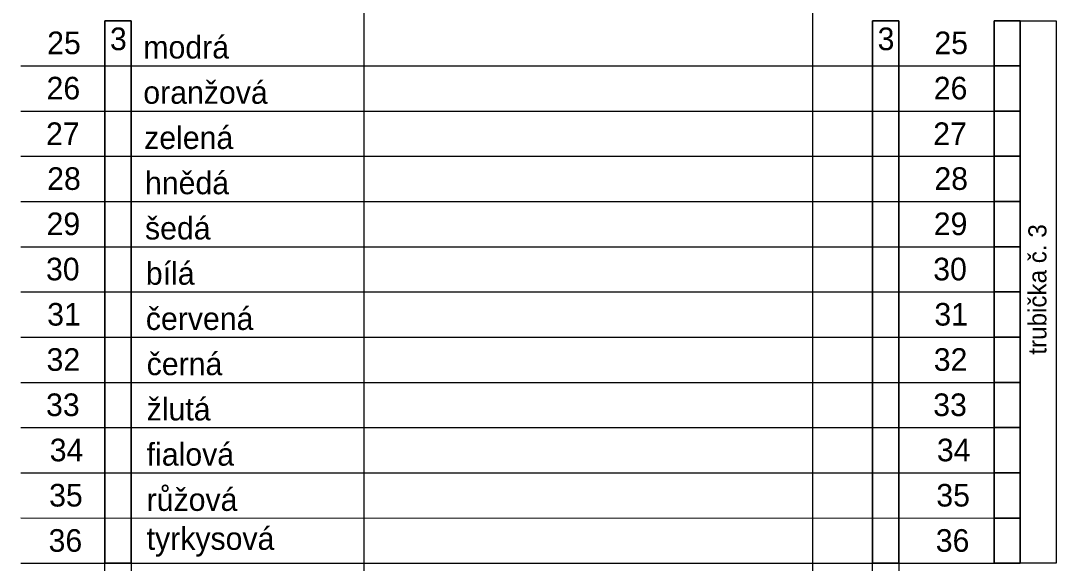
# Model space of a CAD drawing. Extents: x 1901 to 2519, y -3585 to -3154.
# Drawn here: x 2032.8 to 2113, y -3329.7 to -3287.5 of the extents above; entities that cross this region are included whole.
import ezdxf

# ---------------------------------------------------------------- set-up
doc = ezdxf.new("R2010")
doc.units = 0
doc.layers.add('rozvláknění', color=7, linetype='Continuous')

msp = doc.modelspace()

# ---------------------------------------------------------------- linework, layer by layer
at = {"layer": 'rozvláknění'}
for p, q in [((2032.823, -3291.004), (2108.565, -3291.007)), ((2032.823, -3294.523), (2108.565, -3294.525)), ((2032.823, -3298.041), (2108.565, -3298.043)), ((2032.823, -3301.559), (2108.565, -3301.561)), ((2032.823, -3305.077), (2108.565, -3305.079)), ((2032.823, -3308.595), (2108.565, -3308.597)), ((2032.823, -3312.114), (2108.565, -3312.116)), ((2032.823, -3315.632), (2108.565, -3315.634)), ((2032.823, -3319.15), (2108.565, -3319.152)), ((2032.823, -3322.668), (2108.565, -3322.67)), ((2032.823, -3326.186), (2108.565, -3326.188)), ((2032.823, -3329.705), (2108.565, -3329.707))]:
    msp.add_line(p, q, dxfattribs=at)
for points in [[(2014.869, -3178.545), (2059.522, -3178.544), (2059.522, -3570.656), (2014.869, -3570.656)], [(2094.462, -3178.545), (2128.46, -3178.544), (2128.46, -3571.465), (2094.462, -3571.465)], [(2041.391, -3371.961), (2039.35, -3371.961), (2039.35, -3287.488), (2041.391, -3287.488)], [(2041.391, -3329.707), (2039.35, -3329.707), (2039.35, -3287.488), (2041.391, -3287.488)], [(2101.143, -3371.961), (2099.102, -3371.961), (2099.102, -3287.488), (2101.143, -3287.488)], [(2101.143, -3329.707), (2099.102, -3329.707), (2099.102, -3287.488), (2101.143, -3287.488)], [(2108.565, -3287.488), (2110.606, -3287.488), (2110.606, -3291.007), (2108.565, -3291.007)], [(2108.565, -3287.488), (2110.606, -3287.488), (2110.606, -3291.007), (2108.565, -3291.007)], [(2110.606, -3287.488), (2113.393, -3287.488), (2113.393, -3329.703), (2110.606, -3329.703)], [(2108.565, -3291.007), (2110.606, -3291.007), (2110.606, -3294.525), (2108.565, -3294.525)], [(2108.565, -3291.007), (2110.606, -3291.007), (2110.606, -3294.525), (2108.565, -3294.525)], [(2108.565, -3294.525), (2110.606, -3294.525), (2110.606, -3298.043), (2108.565, -3298.043)], [(2108.565, -3294.525), (2110.606, -3294.525), (2110.606, -3298.043), (2108.565, -3298.043)], [(2108.565, -3298.043), (2110.606, -3298.043), (2110.606, -3301.561), (2108.565, -3301.561)], [(2108.565, -3298.043), (2110.606, -3298.043), (2110.606, -3301.561), (2108.565, -3301.561)], [(2108.565, -3301.561), (2110.606, -3301.561), (2110.606, -3305.079), (2108.565, -3305.079)], [(2108.565, -3301.561), (2110.606, -3301.561), (2110.606, -3305.079), (2108.565, -3305.079)], [(2108.565, -3305.079), (2110.606, -3305.079), (2110.606, -3308.597), (2108.565, -3308.597)], [(2108.565, -3305.079), (2110.606, -3305.079), (2110.606, -3308.597), (2108.565, -3308.597)], [(2108.565, -3308.597), (2110.606, -3308.597), (2110.606, -3312.116), (2108.565, -3312.116)], [(2108.565, -3308.597), (2110.606, -3308.597), (2110.606, -3312.116), (2108.565, -3312.116)], [(2108.565, -3312.116), (2110.606, -3312.116), (2110.606, -3315.634), (2108.565, -3315.634)], [(2108.565, -3312.116), (2110.606, -3312.116), (2110.606, -3315.634), (2108.565, -3315.634)], [(2108.565, -3315.634), (2110.606, -3315.634), (2110.606, -3319.152), (2108.565, -3319.152)], [(2108.565, -3315.634), (2110.606, -3315.634), (2110.606, -3319.152), (2108.565, -3319.152)], [(2108.565, -3319.152), (2110.606, -3319.152), (2110.606, -3322.67), (2108.565, -3322.67)], [(2108.565, -3319.152), (2110.606, -3319.152), (2110.606, -3322.67), (2108.565, -3322.67)], [(2108.565, -3322.67), (2110.606, -3322.67), (2110.606, -3326.188), (2108.565, -3326.188)], [(2108.565, -3322.67), (2110.606, -3322.67), (2110.606, -3326.188), (2108.565, -3326.188)], [(2108.565, -3326.188), (2110.606, -3326.188), (2110.606, -3329.707), (2108.565, -3329.707)], [(2108.565, -3326.188), (2110.606, -3326.188), (2110.606, -3329.707), (2108.565, -3329.707)]]:
    msp.add_lwpolyline(points, close=True, dxfattribs=at)
for points in [[(2041.391, -3287.488), (2039.35, -3287.488), (2039.35, -3329.707), (2041.391, -3329.707), (2041.391, -3287.488)], [(2041.391, -3287.488), (2039.35, -3287.488), (2039.35, -3329.707), (2041.391, -3329.707), (2041.391, -3287.488)], [(2041.391, -3287.488), (2039.35, -3287.488), (2039.35, -3329.707), (2041.391, -3329.707), (2041.391, -3287.488)], [(2041.391, -3287.488), (2039.35, -3287.488), (2039.35, -3329.707), (2041.391, -3329.707), (2041.391, -3287.488)], [(2041.391, -3287.488), (2039.35, -3287.488), (2039.35, -3329.707), (2041.391, -3329.707), (2041.391, -3287.488)], [(2041.391, -3287.488), (2039.35, -3287.488), (2039.35, -3329.707), (2041.391, -3329.707), (2041.391, -3287.488)], [(2101.143, -3287.488), (2099.102, -3287.488), (2099.102, -3329.707), (2101.143, -3329.707), (2101.143, -3287.488)], [(2101.143, -3287.488), (2099.102, -3287.488), (2099.102, -3329.707), (2101.143, -3329.707), (2101.143, -3287.488)], [(2101.143, -3287.488), (2099.102, -3287.488), (2099.102, -3329.707), (2101.143, -3329.707), (2101.143, -3287.488)], [(2101.143, -3287.488), (2099.102, -3287.488), (2099.102, -3329.707), (2101.143, -3329.707), (2101.143, -3287.488)], [(2101.143, -3287.488), (2099.102, -3287.488), (2099.102, -3329.707), (2101.143, -3329.707), (2101.143, -3287.488)], [(2101.143, -3287.488), (2099.102, -3287.488), (2099.102, -3329.707), (2101.143, -3329.707), (2101.143, -3287.488)], [(2108.565, -3291.007), (2110.606, -3291.007), (2110.606, -3287.488), (2108.565, -3287.488), (2108.565, -3291.007)], [(2108.565, -3291.007), (2110.606, -3291.007), (2110.606, -3287.488), (2108.565, -3287.488), (2108.565, -3291.007)], [(2108.565, -3291.007), (2110.606, -3291.007), (2110.606, -3287.488), (2108.565, -3287.488), (2108.565, -3291.007)], [(2108.565, -3291.007), (2110.606, -3291.007), (2110.606, -3287.488), (2108.565, -3287.488), (2108.565, -3291.007)], [(2108.565, -3291.007), (2110.606, -3291.007), (2110.606, -3287.488), (2108.565, -3287.488), (2108.565, -3291.007)], [(2108.565, -3291.007), (2110.606, -3291.007), (2110.606, -3287.488), (2108.565, -3287.488), (2108.565, -3291.007)], [(2108.565, -3291.007), (2110.606, -3291.007), (2110.606, -3287.488), (2108.565, -3287.488), (2108.565, -3291.007)], [(2108.565, -3291.007), (2110.606, -3291.007), (2110.606, -3287.488), (2108.565, -3287.488), (2108.565, -3291.007)], [(2108.565, -3291.007), (2110.606, -3291.007), (2110.606, -3287.488), (2108.565, -3287.488), (2108.565, -3291.007)], [(2108.565, -3291.007), (2110.606, -3291.007), (2110.606, -3287.488), (2108.565, -3287.488), (2108.565, -3291.007)], [(2108.565, -3291.004), (2108.565, -3326.204)], [(2108.565, -3294.525), (2110.606, -3294.525), (2110.606, -3291.007), (2108.565, -3291.007), (2108.565, -3294.525)], [(2108.565, -3294.525), (2110.606, -3294.525), (2110.606, -3291.007), (2108.565, -3291.007), (2108.565, -3294.525)], [(2108.565, -3294.525), (2110.606, -3294.525), (2110.606, -3291.007), (2108.565, -3291.007), (2108.565, -3294.525)], [(2108.565, -3294.525), (2110.606, -3294.525), (2110.606, -3291.007), (2108.565, -3291.007), (2108.565, -3294.525)], [(2108.565, -3294.525), (2110.606, -3294.525), (2110.606, -3291.007), (2108.565, -3291.007), (2108.565, -3294.525)], [(2108.565, -3294.525), (2110.606, -3294.525), (2110.606, -3291.007), (2108.565, -3291.007), (2108.565, -3294.525)], [(2108.565, -3294.525), (2110.606, -3294.525), (2110.606, -3291.007), (2108.565, -3291.007), (2108.565, -3294.525)], [(2108.565, -3294.525), (2110.606, -3294.525), (2110.606, -3291.007), (2108.565, -3291.007), (2108.565, -3294.525)], [(2108.565, -3294.525), (2110.606, -3294.525), (2110.606, -3291.007), (2108.565, -3291.007), (2108.565, -3294.525)], [(2108.565, -3294.525), (2110.606, -3294.525), (2110.606, -3291.007), (2108.565, -3291.007), (2108.565, -3294.525)], [(2108.565, -3298.043), (2110.606, -3298.043), (2110.606, -3294.525), (2108.565, -3294.525), (2108.565, -3298.043)], [(2108.565, -3298.043), (2110.606, -3298.043), (2110.606, -3294.525), (2108.565, -3294.525), (2108.565, -3298.043)], [(2108.565, -3298.043), (2110.606, -3298.043), (2110.606, -3294.525), (2108.565, -3294.525), (2108.565, -3298.043)], [(2108.565, -3298.043), (2110.606, -3298.043), (2110.606, -3294.525), (2108.565, -3294.525), (2108.565, -3298.043)], [(2108.565, -3298.043), (2110.606, -3298.043), (2110.606, -3294.525), (2108.565, -3294.525), (2108.565, -3298.043)], [(2108.565, -3298.043), (2110.606, -3298.043), (2110.606, -3294.525), (2108.565, -3294.525), (2108.565, -3298.043)], [(2108.565, -3298.043), (2110.606, -3298.043), (2110.606, -3294.525), (2108.565, -3294.525), (2108.565, -3298.043)], [(2108.565, -3298.043), (2110.606, -3298.043), (2110.606, -3294.525), (2108.565, -3294.525), (2108.565, -3298.043)], [(2108.565, -3298.043), (2110.606, -3298.043), (2110.606, -3294.525), (2108.565, -3294.525), (2108.565, -3298.043)], [(2108.565, -3298.043), (2110.606, -3298.043), (2110.606, -3294.525), (2108.565, -3294.525), (2108.565, -3298.043)], [(2108.565, -3301.561), (2110.606, -3301.561), (2110.606, -3298.043), (2108.565, -3298.043), (2108.565, -3301.561)], [(2108.565, -3301.561), (2110.606, -3301.561), (2110.606, -3298.043), (2108.565, -3298.043), (2108.565, -3301.561)], [(2108.565, -3301.561), (2110.606, -3301.561), (2110.606, -3298.043), (2108.565, -3298.043), (2108.565, -3301.561)], [(2108.565, -3301.561), (2110.606, -3301.561), (2110.606, -3298.043), (2108.565, -3298.043), (2108.565, -3301.561)], [(2108.565, -3301.561), (2110.606, -3301.561), (2110.606, -3298.043), (2108.565, -3298.043), (2108.565, -3301.561)], [(2108.565, -3301.561), (2110.606, -3301.561), (2110.606, -3298.043), (2108.565, -3298.043), (2108.565, -3301.561)], [(2108.565, -3301.561), (2110.606, -3301.561), (2110.606, -3298.043), (2108.565, -3298.043), (2108.565, -3301.561)], [(2108.565, -3301.561), (2110.606, -3301.561), (2110.606, -3298.043), (2108.565, -3298.043), (2108.565, -3301.561)], [(2108.565, -3301.561), (2110.606, -3301.561), (2110.606, -3298.043), (2108.565, -3298.043), (2108.565, -3301.561)], [(2108.565, -3301.561), (2110.606, -3301.561), (2110.606, -3298.043), (2108.565, -3298.043), (2108.565, -3301.561)], [(2108.565, -3305.079), (2110.606, -3305.079), (2110.606, -3301.561), (2108.565, -3301.561), (2108.565, -3305.079)], [(2108.565, -3305.079), (2110.606, -3305.079), (2110.606, -3301.561), (2108.565, -3301.561), (2108.565, -3305.079)], [(2108.565, -3305.079), (2110.606, -3305.079), (2110.606, -3301.561), (2108.565, -3301.561), (2108.565, -3305.079)], [(2108.565, -3305.079), (2110.606, -3305.079), (2110.606, -3301.561), (2108.565, -3301.561), (2108.565, -3305.079)], [(2108.565, -3305.079), (2110.606, -3305.079), (2110.606, -3301.561), (2108.565, -3301.561), (2108.565, -3305.079)], [(2108.565, -3305.079), (2110.606, -3305.079), (2110.606, -3301.561), (2108.565, -3301.561), (2108.565, -3305.079)], [(2108.565, -3305.079), (2110.606, -3305.079), (2110.606, -3301.561), (2108.565, -3301.561), (2108.565, -3305.079)], [(2108.565, -3305.079), (2110.606, -3305.079), (2110.606, -3301.561), (2108.565, -3301.561), (2108.565, -3305.079)], [(2108.565, -3305.079), (2110.606, -3305.079), (2110.606, -3301.561), (2108.565, -3301.561), (2108.565, -3305.079)], [(2108.565, -3305.079), (2110.606, -3305.079), (2110.606, -3301.561), (2108.565, -3301.561), (2108.565, -3305.079)], [(2108.565, -3308.597), (2110.606, -3308.597), (2110.606, -3305.079), (2108.565, -3305.079), (2108.565, -3308.597)], [(2108.565, -3308.597), (2110.606, -3308.597), (2110.606, -3305.079), (2108.565, -3305.079), (2108.565, -3308.597)], [(2108.565, -3308.597), (2110.606, -3308.597), (2110.606, -3305.079), (2108.565, -3305.079), (2108.565, -3308.597)], [(2108.565, -3308.597), (2110.606, -3308.597), (2110.606, -3305.079), (2108.565, -3305.079), (2108.565, -3308.597)], [(2108.565, -3308.597), (2110.606, -3308.597), (2110.606, -3305.079), (2108.565, -3305.079), (2108.565, -3308.597)], [(2108.565, -3308.597), (2110.606, -3308.597), (2110.606, -3305.079), (2108.565, -3305.079), (2108.565, -3308.597)], [(2108.565, -3308.597), (2110.606, -3308.597), (2110.606, -3305.079), (2108.565, -3305.079), (2108.565, -3308.597)], [(2108.565, -3308.597), (2110.606, -3308.597), (2110.606, -3305.079), (2108.565, -3305.079), (2108.565, -3308.597)], [(2108.565, -3308.597), (2110.606, -3308.597), (2110.606, -3305.079), (2108.565, -3305.079), (2108.565, -3308.597)], [(2108.565, -3308.597), (2110.606, -3308.597), (2110.606, -3305.079), (2108.565, -3305.079), (2108.565, -3308.597)], [(2108.565, -3312.116), (2110.606, -3312.116), (2110.606, -3308.597), (2108.565, -3308.597), (2108.565, -3312.116)], [(2108.565, -3312.116), (2110.606, -3312.116), (2110.606, -3308.597), (2108.565, -3308.597), (2108.565, -3312.116)], [(2108.565, -3312.116), (2110.606, -3312.116), (2110.606, -3308.597), (2108.565, -3308.597), (2108.565, -3312.116)], [(2108.565, -3312.116), (2110.606, -3312.116), (2110.606, -3308.597), (2108.565, -3308.597), (2108.565, -3312.116)], [(2108.565, -3312.116), (2110.606, -3312.116), (2110.606, -3308.597), (2108.565, -3308.597), (2108.565, -3312.116)], [(2108.565, -3312.116), (2110.606, -3312.116), (2110.606, -3308.597), (2108.565, -3308.597), (2108.565, -3312.116)], [(2108.565, -3312.116), (2110.606, -3312.116), (2110.606, -3308.597), (2108.565, -3308.597), (2108.565, -3312.116)], [(2108.565, -3312.116), (2110.606, -3312.116), (2110.606, -3308.597), (2108.565, -3308.597), (2108.565, -3312.116)], [(2108.565, -3312.116), (2110.606, -3312.116), (2110.606, -3308.597), (2108.565, -3308.597), (2108.565, -3312.116)], [(2108.565, -3312.116), (2110.606, -3312.116), (2110.606, -3308.597), (2108.565, -3308.597), (2108.565, -3312.116)], [(2108.565, -3315.634), (2110.606, -3315.634), (2110.606, -3312.116), (2108.565, -3312.116), (2108.565, -3315.634)], [(2108.565, -3315.634), (2110.606, -3315.634), (2110.606, -3312.116), (2108.565, -3312.116), (2108.565, -3315.634)], [(2108.565, -3315.634), (2110.606, -3315.634), (2110.606, -3312.116), (2108.565, -3312.116), (2108.565, -3315.634)], [(2108.565, -3315.634), (2110.606, -3315.634), (2110.606, -3312.116), (2108.565, -3312.116), (2108.565, -3315.634)], [(2108.565, -3315.634), (2110.606, -3315.634), (2110.606, -3312.116), (2108.565, -3312.116), (2108.565, -3315.634)], [(2108.565, -3315.634), (2110.606, -3315.634), (2110.606, -3312.116), (2108.565, -3312.116), (2108.565, -3315.634)], [(2108.565, -3315.634), (2110.606, -3315.634), (2110.606, -3312.116), (2108.565, -3312.116), (2108.565, -3315.634)], [(2108.565, -3315.634), (2110.606, -3315.634), (2110.606, -3312.116), (2108.565, -3312.116), (2108.565, -3315.634)], [(2108.565, -3315.634), (2110.606, -3315.634), (2110.606, -3312.116), (2108.565, -3312.116), (2108.565, -3315.634)], [(2108.565, -3315.634), (2110.606, -3315.634), (2110.606, -3312.116), (2108.565, -3312.116), (2108.565, -3315.634)], [(2108.565, -3319.152), (2110.606, -3319.152), (2110.606, -3315.634), (2108.565, -3315.634), (2108.565, -3319.152)], [(2108.565, -3319.152), (2110.606, -3319.152), (2110.606, -3315.634), (2108.565, -3315.634), (2108.565, -3319.152)], [(2108.565, -3319.152), (2110.606, -3319.152), (2110.606, -3315.634), (2108.565, -3315.634), (2108.565, -3319.152)], [(2108.565, -3319.152), (2110.606, -3319.152), (2110.606, -3315.634), (2108.565, -3315.634), (2108.565, -3319.152)], [(2108.565, -3319.152), (2110.606, -3319.152), (2110.606, -3315.634), (2108.565, -3315.634), (2108.565, -3319.152)], [(2108.565, -3319.152), (2110.606, -3319.152), (2110.606, -3315.634), (2108.565, -3315.634), (2108.565, -3319.152)], [(2108.565, -3319.152), (2110.606, -3319.152), (2110.606, -3315.634), (2108.565, -3315.634), (2108.565, -3319.152)], [(2108.565, -3319.152), (2110.606, -3319.152), (2110.606, -3315.634), (2108.565, -3315.634), (2108.565, -3319.152)], [(2108.565, -3319.152), (2110.606, -3319.152), (2110.606, -3315.634), (2108.565, -3315.634), (2108.565, -3319.152)], [(2108.565, -3319.152), (2110.606, -3319.152), (2110.606, -3315.634), (2108.565, -3315.634), (2108.565, -3319.152)], [(2108.565, -3322.67), (2110.606, -3322.67), (2110.606, -3319.152), (2108.565, -3319.152), (2108.565, -3322.67)], [(2108.565, -3322.67), (2110.606, -3322.67), (2110.606, -3319.152), (2108.565, -3319.152), (2108.565, -3322.67)], [(2108.565, -3322.67), (2110.606, -3322.67), (2110.606, -3319.152), (2108.565, -3319.152), (2108.565, -3322.67)], [(2108.565, -3322.67), (2110.606, -3322.67), (2110.606, -3319.152), (2108.565, -3319.152), (2108.565, -3322.67)], [(2108.565, -3322.67), (2110.606, -3322.67), (2110.606, -3319.152), (2108.565, -3319.152), (2108.565, -3322.67)], [(2108.565, -3322.67), (2110.606, -3322.67), (2110.606, -3319.152), (2108.565, -3319.152), (2108.565, -3322.67)], [(2108.565, -3322.67), (2110.606, -3322.67), (2110.606, -3319.152), (2108.565, -3319.152), (2108.565, -3322.67)], [(2108.565, -3322.67), (2110.606, -3322.67), (2110.606, -3319.152), (2108.565, -3319.152), (2108.565, -3322.67)], [(2108.565, -3322.67), (2110.606, -3322.67), (2110.606, -3319.152), (2108.565, -3319.152), (2108.565, -3322.67)], [(2108.565, -3322.67), (2110.606, -3322.67), (2110.606, -3319.152), (2108.565, -3319.152), (2108.565, -3322.67)], [(2108.565, -3326.188), (2110.606, -3326.188), (2110.606, -3322.67), (2108.565, -3322.67), (2108.565, -3326.188)], [(2108.565, -3326.188), (2110.606, -3326.188), (2110.606, -3322.67), (2108.565, -3322.67), (2108.565, -3326.188)], [(2108.565, -3326.188), (2110.606, -3326.188), (2110.606, -3322.67), (2108.565, -3322.67), (2108.565, -3326.188)], [(2108.565, -3326.188), (2110.606, -3326.188), (2110.606, -3322.67), (2108.565, -3322.67), (2108.565, -3326.188)], [(2108.565, -3326.188), (2110.606, -3326.188), (2110.606, -3322.67), (2108.565, -3322.67), (2108.565, -3326.188)], [(2108.565, -3326.188), (2110.606, -3326.188), (2110.606, -3322.67), (2108.565, -3322.67), (2108.565, -3326.188)], [(2108.565, -3326.188), (2110.606, -3326.188), (2110.606, -3322.67), (2108.565, -3322.67), (2108.565, -3326.188)], [(2108.565, -3326.188), (2110.606, -3326.188), (2110.606, -3322.67), (2108.565, -3322.67), (2108.565, -3326.188)], [(2108.565, -3326.188), (2110.606, -3326.188), (2110.606, -3322.67), (2108.565, -3322.67), (2108.565, -3326.188)], [(2108.565, -3326.188), (2110.606, -3326.188), (2110.606, -3322.67), (2108.565, -3322.67), (2108.565, -3326.188)], [(2108.565, -3329.707), (2110.606, -3329.707), (2110.606, -3326.188), (2108.565, -3326.188), (2108.565, -3329.707)], [(2108.565, -3329.707), (2110.606, -3329.707), (2110.606, -3326.188), (2108.565, -3326.188), (2108.565, -3329.707)], [(2108.565, -3329.707), (2110.606, -3329.707), (2110.606, -3326.188), (2108.565, -3326.188), (2108.565, -3329.707)], [(2108.565, -3329.707), (2110.606, -3329.707), (2110.606, -3326.188), (2108.565, -3326.188), (2108.565, -3329.707)], [(2108.565, -3329.707), (2110.606, -3329.707), (2110.606, -3326.188), (2108.565, -3326.188), (2108.565, -3329.707)], [(2108.565, -3329.707), (2110.606, -3329.707), (2110.606, -3326.188), (2108.565, -3326.188), (2108.565, -3329.707)], [(2108.565, -3329.707), (2110.606, -3329.707), (2110.606, -3326.188), (2108.565, -3326.188), (2108.565, -3329.707)], [(2108.565, -3329.707), (2110.606, -3329.707), (2110.606, -3326.188), (2108.565, -3326.188), (2108.565, -3329.707)], [(2108.565, -3329.707), (2110.606, -3329.707), (2110.606, -3326.188), (2108.565, -3326.188), (2108.565, -3329.707)], [(2108.565, -3329.707), (2110.606, -3329.707), (2110.606, -3326.188), (2108.565, -3326.188), (2108.565, -3329.707)]]:
    msp.add_lwpolyline(points, dxfattribs=at)

# ---------------------------------------------------------------- texts
for s, p in [('25', (2034.862, -3290.095)), ('3', (2039.749, -3289.784)), ('3', (2039.749, -3289.784)), ('modrá', (2042.346, -3290.433)), ('3', (2099.501, -3289.784)), ('3', (2099.501, -3289.784)), ('25', (2103.919, -3290.095)), ('26', (2034.815, -3293.615)), ('26', (2103.872, -3293.615)), ('oranžová', (2042.346, -3293.953)), ('27', (2034.773, -3297.165)), ('zelená', (2042.411, -3297.473)), ('27', (2103.83, -3297.165)), ('28', (2034.862, -3300.655)), ('hnědá', (2042.477, -3300.993)), ('28', (2103.919, -3300.655)), ('29', (2034.815, -3304.175)), ('šedá', (2042.477, -3304.513)), ('29', (2103.872, -3304.175)), ('30', (2034.773, -3307.695)), ('bílá', (2042.542, -3308.033)), ('30', (2103.83, -3307.695)), ('31', (2034.862, -3311.215)), ('31', (2103.919, -3311.215)), ('červená', (2042.542, -3311.553)), ('32', (2034.815, -3314.735)), ('černá', (2042.608, -3315.073)), ('32', (2103.872, -3314.735)), ('33', (2034.773, -3318.255)), ('žlutá', (2042.608, -3318.593)), ('33', (2103.83, -3318.255)), ('34', (2035.061, -3321.775)), ('34', (2104.118, -3321.775)), ('fialová', (2042.608, -3322.113)), ('35', (2035.014, -3325.295)), ('růžová', (2042.608, -3325.633)), ('35', (2104.071, -3325.295)), ('36', (2034.972, -3328.815)), ('tyrkysová', (2042.608, -3328.665)), ('36', (2104.029, -3328.815))]:
    msp.add_text(s, height=1.76, dxfattribs=at).set_placement(p)
msp.add_text('trubička č. 3', height=1.408, rotation=90, dxfattribs=at).set_placement((2112.641, -3313.477))

doc.saveas('drawing.dxf')
